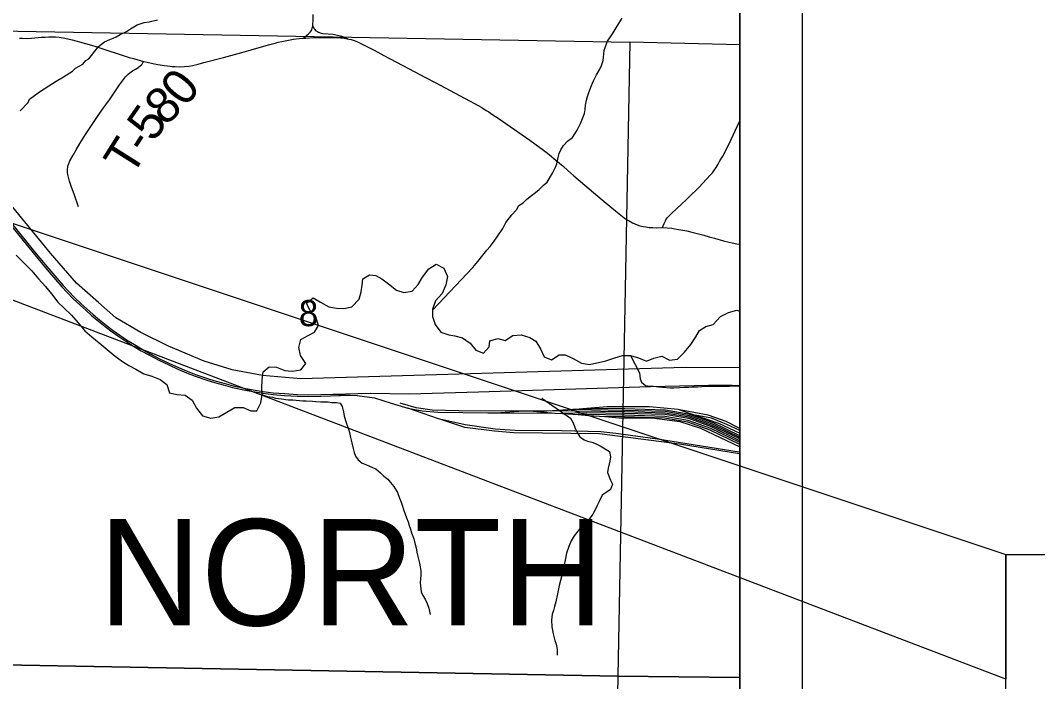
# Model space of a CAD drawing. Extents: x -7.1 to 34, y 0 to 22.
# Drawn here: x 7.746 to 9.377, y 15.673 to 16.733 of the extents above; entities that cross this region are included whole.
import ezdxf

# ---------------------------------------------------------------- set-up
doc = ezdxf.new("R2010")
doc.units = 0
for name, color, linetype in [('GM_X_Major_River', 7, 'Continuous'), ('GM_X_Minor_River', 7, 'Continuous'), ('GM_X_Rail_Line', 7, 'Continuous'), ('GM_X_Section', 7, 'Continuous'), ('GM_X_Section_Text', 7, 'Continuous'), ('GM_X_State_Route', 7, 'Continuous'), ('GM_X_Township_Road', 7, 'Continuous'), ('GM_X_Township_Road_Text', 7, 'Continuous'), ('GM_X_Township_Text', 7, 'Continuous'), ('GM_X_Unincorporated', 7, 'Continuous'), ('SH_Cut_Line', 7, 'Continuous'), ('SH_Data', 7, 'Continuous'), ('SH_Text', 7, 'Continuous')]:
    doc.layers.add(name, color=color, linetype=linetype)

msp = doc.modelspace()

# ---------------------------------------------------------------- linework, layer by layer
at = {"layer": 'GM_X_Major_River'}
for points in [[(7.7396, 16.3561), (7.7523, 16.3433), (7.7646, 16.3309), (7.7757, 16.3182), (7.7865, 16.3058), (7.7962, 16.2942), (7.8066, 16.281), (7.8162, 16.272), (7.8281, 16.26), (7.8393, 16.2477), (7.8497, 16.2349), (7.8608, 16.2252), (7.8727, 16.2158), (7.8857, 16.205), (7.8984, 16.1942), (7.9103, 16.186), (7.9202, 16.1796), (7.9313, 16.1737), (7.9443, 16.1663), (7.9569, 16.1623), (7.9703, 16.1571), (7.9814, 16.1489), (7.9857, 16.1357), (7.9975, 16.1328), (8.0104, 16.1318), (8.0219, 16.124), (8.0289, 16.1108), (8.0386, 16.0988), (8.0515, 16.0948), (8.0644, 16.0972), (8.0772, 16.1046), (8.0904, 16.1119), (8.1034, 16.1121), (8.1159, 16.107), (8.1254, 16.1067), (8.1321, 16.1193), (8.1342, 16.133), (8.1337, 16.1432), (8.1343, 16.1565), (8.1357, 16.1694), (8.1455, 16.1775), (8.1569, 16.1765), (8.1702, 16.1713), (8.1824, 16.1704), (8.196, 16.1724), (8.2039, 16.1828), (8.1957, 16.1956), (8.1926, 16.208), (8.1958, 16.221), (8.2079, 16.2276), (8.2177, 16.2326), (8.2244, 16.2437), (8.2205, 16.2554), (8.2112, 16.2671), (8.2053, 16.2791), (8.2159, 16.2876), (8.2274, 16.2809), (8.2407, 16.2735), (8.2533, 16.2714), (8.2651, 16.2708), (8.2776, 16.2732), (8.2896, 16.2855), (8.2928, 16.2973), (8.2946, 16.3079), (8.2956, 16.3182), (8.3062, 16.3247), (8.3165, 16.3234), (8.326, 16.3182), (8.3364, 16.3103), (8.3494, 16.3002), (8.3612, 16.2962), (8.3745, 16.2983), (8.3842, 16.309), (8.3909, 16.3212), (8.401, 16.3343), (8.4131, 16.342), (8.4253, 16.3353), (8.4312, 16.3221), (8.4283, 16.3088), (8.4228, 16.2947), (8.4119, 16.2832), (8.4071, 16.2699), (8.4073, 16.2581), (8.4112, 16.2449), (8.4205, 16.2328), (8.4334, 16.2285), (8.443, 16.2271), (8.4552, 16.2238), (8.4675, 16.2154)], [(8.4675, 16.2154), (8.4766, 16.2038), (8.4888, 16.199), (8.4981, 16.2094), (8.4991, 16.2189), (8.5119, 16.2225), (8.5237, 16.2197), (8.5357, 16.2275), (8.5493, 16.2285), (8.563, 16.2245), (8.573, 16.2182), (8.5803, 16.2059), (8.5862, 16.1934), (8.5977, 16.1887), (8.61, 16.1965), (8.6199, 16.1963), (8.6325, 16.1904), (8.6462, 16.1831), (8.6591, 16.181), (8.6848, 16.1867), (8.6995, 16.1915), (8.7119, 16.1955), (8.7248, 16.1953), (8.7373, 16.1918), (8.7503, 16.1863), (8.7619, 16.1914), (8.7748, 16.1943), (8.787, 16.188), (8.8002, 16.1894), (8.8114, 16.2009), (8.8214, 16.2129), (8.8292, 16.2255), (8.8354, 16.2355), (8.8452, 16.2421), (8.8569, 16.2453), (8.8688, 16.258), (8.8815, 16.2646), (8.8951, 16.2679), (8.9, 16.2664)]]:
    msp.add_lwpolyline(points, dxfattribs=at)
at = {"layer": 'GM_X_Minor_River'}
for points in [[(8.4071, 16.268), (8.4718, 16.3367), (8.4798, 16.3461), (8.4879, 16.3564), (8.494, 16.364), (8.4997, 16.37), (8.5058, 16.3784), (8.5119, 16.3874), (8.5199, 16.3988), (8.5245, 16.4087), (8.5344, 16.4208), (8.5417, 16.4288), (8.5455, 16.436), (8.5523, 16.4401), (8.5581, 16.4454), (8.5638, 16.45), (8.5725, 16.4568), (8.5782, 16.4617), (8.5847, 16.4678), (8.5908, 16.4734), (8.5996, 16.4879), (8.6046, 16.497), (8.6065, 16.5026), (8.6088, 16.5129), (8.6104, 16.519), (8.6131, 16.525), (8.6173, 16.5319), (8.6237, 16.5387), (8.6314, 16.5447), (8.6356, 16.5508), (8.639, 16.5565), (8.6444, 16.5671), (8.6478, 16.5755), (8.6509, 16.5834), (8.6517, 16.5895), (8.6524, 16.5967), (8.654, 16.6047), (8.6559, 16.6104), (8.6579, 16.6172), (8.6621, 16.6283), (8.6651, 16.6358), (8.6701, 16.6453), (8.6755, 16.6541), (8.6782, 16.6601), (8.6805, 16.6681), (8.682, 16.6787), (8.6824, 16.6844), (8.6844, 16.6905), (8.6878, 16.6992), (8.6924, 16.7064), (8.6966, 16.7125), (8.7016, 16.7205), (8.7058, 16.7273), (8.7111, 16.736)], [(7.7463, 16.5876), (7.759, 16.6011), (7.7608, 16.6061), (7.7773, 16.6178), (7.7919, 16.6275), (7.8039, 16.6349), (7.8155, 16.642), (7.8302, 16.6509), (7.8347, 16.656), (7.8463, 16.6626), (7.8511, 16.6684), (7.856, 16.6707), (7.8605, 16.6765), (7.8657, 16.6831), (7.8716, 16.6904), (7.881, 16.6982), (7.8896, 16.7021), (7.8949, 16.7041), (7.8998, 16.7064), (7.9062, 16.71), (7.9167, 16.7147), (7.9227, 16.719), (7.9336, 16.7256), (7.9449, 16.7292), (7.9528, 16.7301), (7.9664, 16.7333)], [(8.7248, 16.1953), (8.739, 16.1674), (8.7401, 16.1582), (8.742, 16.1525), (8.7484, 16.1476), (8.7556, 16.1464), (8.7617, 16.1464), (8.77, 16.1452), (8.7761, 16.1444), (8.7882, 16.1436), (8.7939, 16.1436), (8.8034, 16.1439), (8.8114, 16.1447), (8.8182, 16.1446), (8.8239, 16.145), (8.8326, 16.1454), (8.8383, 16.1457), (8.847, 16.1461), (8.8599, 16.1464), (8.8835, 16.1463), (8.8952, 16.1467), (8.9, 16.1464)], [(8.1342, 16.133), (8.1346, 16.1322), (8.1425, 16.1297), (8.1505, 16.1286), (8.1555, 16.1272), (8.1653, 16.1258), (8.1756, 16.1244), (8.1831, 16.1242), (8.1937, 16.1232), (8.1991, 16.1229), (8.2047, 16.123), (8.2146, 16.1224), (8.2203, 16.1217), (8.2282, 16.1211), (8.2335, 16.1211), (8.2396, 16.1209), (8.2457, 16.1202), (8.2532, 16.1199), (8.2589, 16.1189), (8.2624, 16.1136), (8.2644, 16.1053), (8.2657, 16.098), (8.2685, 16.0882), (8.2724, 16.0772), (8.274, 16.0719), (8.2756, 16.0639), (8.2777, 16.0552), (8.2797, 16.0461), (8.2813, 16.04), (8.2836, 16.034), (8.2879, 16.028), (8.2944, 16.0231), (8.3005, 16.0205), (8.3112, 16.0161), (8.3161, 16.0139), (8.3238, 16.0076), (8.3292, 16.002), (8.3353, 15.9971), (8.3399, 15.9918), (8.3453, 15.9855), (8.3508, 15.9756), (8.3543, 15.9669), (8.3567, 15.9601), (8.359, 15.9537), (8.3606, 15.9484), (8.3634, 15.9412), (8.3654, 15.9351), (8.3681, 15.9287), (8.3697, 15.923), (8.3717, 15.917), (8.3733, 15.9113), (8.3772, 15.9014), (8.3796, 15.8927), (8.3812, 15.8874), (8.3821, 15.8802), (8.3829, 15.8753), (8.3845, 15.8688), (8.3861, 15.8628), (8.3873, 15.8567), (8.3886, 15.8502), (8.3883, 15.8434), (8.388, 15.8373), (8.3873, 15.8312), (8.3882, 15.8213), (8.389, 15.8164), (8.3918, 15.8107), (8.3956, 15.8051), (8.3988, 15.7979), (8.4015, 15.7907), (8.4024, 15.7857), (8.4032, 15.7804)], [(8.5826, 16.1271), (8.6283, 16.0948), (8.6324, 16.0875), (8.6354, 16.0799), (8.6384, 16.0731), (8.6433, 16.0651), (8.6501, 16.0605), (8.6558, 16.0582), (8.6626, 16.0563), (8.6698, 16.0536), (8.6759, 16.0505), (8.691, 16.0414), (8.6925, 16.033), (8.6917, 16.0258), (8.689, 16.0148), (8.6875, 16.0079), (8.6923, 15.9957), (8.6957, 15.9893), (8.6923, 15.9809), (8.6858, 15.9756), (8.6793, 15.9715), (8.6743, 15.9616), (8.6709, 15.9552), (8.6678, 15.9483), (8.6644, 15.9411), (8.6575, 15.9313), (8.6514, 15.9267), (8.645, 15.9203), (8.6404, 15.9138), (8.6343, 15.9063), (8.6297, 15.8983), (8.6258, 15.8892), (8.622, 15.8786), (8.6201, 15.8672), (8.6185, 15.8603), (8.6173, 15.8539), (8.6143, 15.8429), (8.61, 15.8266), (8.6073, 15.8133), (8.605, 15.8007), (8.603, 15.7931), (8.6011, 15.7867), (8.5988, 15.7806), (8.598, 15.7711), (8.5987, 15.7605), (8.6006, 15.7494), (8.6032, 15.7388), (8.6054, 15.7327), (8.6069, 15.724), (8.6072, 15.715)]]:
    msp.add_lwpolyline(points, dxfattribs=at)
at = {"layer": 'GM_X_Rail_Line'}
for p, q in [((8.2477, 16.1335), (8.2754, 16.1318)), ((8.5093, 16.1033), (8.5453, 16.1063)), ((8.5093, 16.1033), (8.6038, 16.1028)), ((8.5687, 16.1062), (8.5453, 16.1063)), ((8.5687, 16.1062), (8.6038, 16.1028)), ((8.6038, 16.1028), (8.6158, 16.1027)), ((8.6158, 16.1027), (8.6405, 16.1007)), ((8.6545, 16.1105), (8.6359, 16.109)), ((8.8032, 16.1084), (8.8285, 16.0998))]:
    msp.add_line(p, q, dxfattribs=at)
for points in [[(8.9, 16.1755), (8.8125, 16.176), (8.196, 16.1579), (8.1347, 16.1635), (8.0861, 16.1725), (8.0408, 16.1866), (7.984, 16.2103), (7.9395, 16.2321), (7.8997, 16.2558), (7.8718, 16.2805), (7.8362, 16.3111), (7.7949, 16.3595), (7.593, 16.6046)], [(7.7073, 16.433), (7.767, 16.3599), (7.7896, 16.3326), (7.8026, 16.3173), (7.8131, 16.3055), (7.8216, 16.2964), (7.8312, 16.2864), (7.8418, 16.2764), (7.8511, 16.2679), (7.8611, 16.259), (7.8715, 16.2503), (7.8823, 16.2418), (7.8938, 16.2332), (7.9044, 16.2259), (7.9153, 16.2183), (7.9277, 16.2105), (7.9402, 16.2031), (7.9532, 16.1957), (7.9683, 16.1877), (7.9842, 16.1802), (7.9986, 16.1735), (8.0125, 16.1678), (8.0264, 16.1625), (8.0454, 16.1559), (8.0576, 16.1521), (8.0716, 16.1482), (8.0867, 16.1442), (8.1045, 16.1403), (8.1191, 16.1375), (8.1354, 16.1348), (8.1517, 16.133), (8.1696, 16.1315), (8.1904, 16.1302), (8.2088, 16.1298), (8.2283, 16.1301), (8.2754, 16.1318)], [(7.7095, 16.4348), (7.7692, 16.3616), (7.7918, 16.3344), (7.8048, 16.3192), (7.8152, 16.3074), (7.8236, 16.2983), (7.8332, 16.2885), (7.8438, 16.2784), (7.853, 16.27), (7.8629, 16.2611), (7.8733, 16.2525), (7.884, 16.244), (7.8954, 16.2355), (7.906, 16.2282), (7.9168, 16.2207), (7.9292, 16.2129), (7.9416, 16.2055), (7.9545, 16.1981), (7.9695, 16.1902), (7.9854, 16.1827), (7.9997, 16.1761), (8.0136, 16.1705), (8.0274, 16.1652), (8.0463, 16.1586), (8.0584, 16.1548), (8.0724, 16.151), (8.0874, 16.147), (8.1051, 16.143), (8.1196, 16.1403), (8.1358, 16.1376), (8.1519, 16.1358), (8.1698, 16.1344), (8.1905, 16.133), (8.2088, 16.1326), (8.2282, 16.1329), (8.3074, 16.1351), (8.3695, 16.1341), (8.4807, 16.1372), (8.6372, 16.1419), (8.7565, 16.1456), (8.8266, 16.1473), (8.8496, 16.1477), (8.8703, 16.148), (8.8877, 16.148), (8.9, 16.1473)], [(8.2754, 16.1318), (8.2864, 16.1312), (8.314, 16.1276), (8.341, 16.1188), (8.3674, 16.1112)], [(8.5453, 16.1063), (8.4493, 16.1067), (8.4066, 16.108), (8.381, 16.1114), (8.3555, 16.1192)], [(8.419, 16.0934), (8.417, 16.0938), (8.3674, 16.1112)], [(8.3674, 16.1112), (8.3906, 16.1068), (8.4157, 16.1047), (8.496, 16.1034), (8.5093, 16.1033)], [(8.5994, 16.1067), (8.5902, 16.1061), (8.5687, 16.1062)], [(8.6359, 16.109), (8.6321, 16.1087), (8.5994, 16.1067)], [(8.9, 16.0616), (8.8552, 16.0833), (8.8185, 16.0965), (8.7801, 16.103), (8.7152, 16.105), (8.5994, 16.1067)], [(8.9, 16.0589), (8.8543, 16.0811), (8.8179, 16.0942), (8.7798, 16.1007), (8.7151, 16.1027), (8.6544, 16.1034), (8.6158, 16.1027)], [(8.9, 16.0642), (8.8561, 16.0855), (8.8191, 16.0988), (8.7803, 16.1054), (8.7152, 16.1074), (8.6359, 16.109)], [(8.9, 16.0558), (8.8532, 16.0785), (8.8172, 16.0915), (8.7795, 16.0979), (8.7151, 16.0998), (8.6544, 16.1006), (8.6405, 16.1007)], [(8.6405, 16.1007), (8.6575, 16.0994), (8.6834, 16.0974)], [(8.8032, 16.1084), (8.8008, 16.1088), (8.7551, 16.1133), (8.6874, 16.1131), (8.6545, 16.1105)], [(8.9, 16.0668), (8.8571, 16.0877), (8.8198, 16.1011), (8.7805, 16.1077), (8.7153, 16.1097), (8.6545, 16.1105)], [(8.9, 16.0786), (8.8781, 16.0895), (8.8489, 16.1), (8.8032, 16.1084)], [(8.9, 16.0751), (8.8792, 16.085), (8.8542, 16.0951), (8.8285, 16.0998)], [(8.8285, 16.0998), (8.8659, 16.0871), (8.8997, 16.0711), (8.9, 16.071)], [(8.9, 16.0376), (8.8994, 16.0377), (8.8031, 16.0533), (8.675, 16.0698), (8.5375, 16.0714), (8.5064, 16.074), (8.4589, 16.0802), (8.419, 16.0934)], [(8.9, 16.0404), (8.8988, 16.0407), (8.7679, 16.0615), (8.7013, 16.0704), (8.6769, 16.0733), (8.6147, 16.0746), (8.5397, 16.0752), (8.5076, 16.0772), (8.4593, 16.0845), (8.419, 16.0934)], [(8.9, 16.0526), (8.8521, 16.0759), (8.8165, 16.0887), (8.7793, 16.095), (8.715, 16.097), (8.6834, 16.0974)], [(8.6834, 16.0974), (8.7065, 16.0956), (8.7589, 16.0954), (8.8036, 16.0894), (8.8366, 16.0789), (8.9, 16.049)]]:
    msp.add_lwpolyline(points, dxfattribs=at)
at = {"layer": 'GM_X_Section'}
for points in [[(7.7117, 16.7156), (8.7236, 16.6977), (8.7045, 15.6816), (7.6901, 15.7003)], [(7.6901, 15.7003), (8.7045, 15.6816), (8.6861, 14.6719), (7.6641, 14.6933)]]:
    msp.add_lwpolyline(points, close=True, dxfattribs=at)
at = {"layer": 'GM_X_State_Route'}
for points in [[(7.7448, 16.704), (7.749, 16.7038), (7.7564, 16.7037), (7.7643, 16.7041), (7.7801, 16.7054), (7.786, 16.7058), (7.792, 16.7061), (7.7964, 16.7061), (7.8027, 16.7059), (7.8084, 16.7054), (7.8148, 16.7045), (7.8223, 16.7031), (7.8293, 16.7015), (7.841, 16.6984), (7.8603, 16.6928), (7.8673, 16.6906), (7.9207, 16.6733), (7.9276, 16.6712), (7.944, 16.6668), (7.9497, 16.6654), (7.9586, 16.6633), (7.9668, 16.6618), (7.9776, 16.6602), (7.986, 16.6589), (7.9892, 16.6586), (7.9948, 16.6584), (8.0022, 16.6583), (8.0097, 16.6586), (8.0167, 16.6594), (8.0225, 16.6604), (8.0316, 16.6624), (8.0404, 16.6648), (8.0721, 16.6729), (8.1017, 16.6812), (8.1162, 16.6851), (8.1443, 16.6932), (8.1549, 16.6962), (8.1596, 16.6974), (8.1654, 16.6988), (8.1788, 16.7014), (8.1842, 16.7022), (8.1932, 16.7033), (8.2, 16.7039), (8.2037, 16.7042), (8.2168, 16.7049), (8.239, 16.7052), (8.2525, 16.7049), (8.2597, 16.7045), (8.2653, 16.7039), (8.2706, 16.703)], [(8.2706, 16.703), (8.2731, 16.7026), (8.2766, 16.7017), (8.2814, 16.7002), (8.2871, 16.6981), (8.2913, 16.6962), (8.3052, 16.6892), (8.3138, 16.6847), (8.3293, 16.6765), (8.3687, 16.6555), (8.396, 16.6408), (8.4124, 16.6323), (8.4584, 16.6081), (8.4756, 16.599), (8.4862, 16.5928), (8.4934, 16.5882), (8.4973, 16.5857), (8.5024, 16.5823), (8.5126, 16.5757), (8.5317, 16.5625), (8.5509, 16.5492), (8.5632, 16.5405), (8.5736, 16.5332), (8.583, 16.5261), (8.5915, 16.5197), (8.605, 16.5085), (8.6165, 16.4987), (8.6242, 16.4918), (8.6339, 16.4832), (8.6581, 16.4623), (8.6791, 16.445), (8.6947, 16.432), (8.7063, 16.4226), (8.712, 16.4182), (8.7168, 16.4146), (8.7225, 16.411), (8.7277, 16.4081), (8.7313, 16.4064), (8.7353, 16.4048), (8.7397, 16.4034), (8.7449, 16.4022), (8.7494, 16.4014), (8.7547, 16.4008), (8.76, 16.4004), (8.7661, 16.4003), (8.7758, 16.4004)], [(8.7758, 16.4004), (8.7835, 16.4001), (8.7909, 16.3993), (8.7959, 16.3986), (8.8018, 16.3976), (8.8053, 16.3969), (8.8147, 16.3952), (8.8253, 16.3925), (8.842, 16.3881), (8.8505, 16.3856), (8.859, 16.3833), (8.8737, 16.3792), (8.8826, 16.377), (8.8877, 16.3759), (8.8951, 16.3746), (8.9, 16.3738)]]:
    msp.add_lwpolyline(points, dxfattribs=at)
at = {"layer": 'GM_X_Township_Road'}
msp.add_lwpolyline([(6.633, 14.1), (8.9, 14.1), (8.9, 17.7079), (8.6668, 17.7136), (8.4472, 17.7189), (7.7202, 17.7285), (6.7118, 17.7486), (6.7058, 17.2839), (6.6822, 16.3488), (6.6748, 15.9993), (6.6586, 15.2372), (6.6565, 15.1357)], close=True, dxfattribs=at)
for points in [[(8.2, 16.7039), (8.203, 16.7061), (8.2058, 16.7086), (8.2086, 16.7111), (8.2108, 16.7134), (8.213, 16.7162), (8.2139, 16.718), (8.2144, 16.7199), (8.2152, 16.7232), (8.2154, 16.7277), (8.2156, 16.7307), (8.216, 16.7421)], [(8.2152, 16.7232), (8.2165, 16.7206), (8.218, 16.7182), (8.2202, 16.716), (8.2225, 16.7145), (8.2245, 16.7135), (8.2286, 16.7122), (8.2314, 16.7115), (8.2477, 16.7102), (8.2499, 16.7099), (8.2595, 16.7079), (8.2618, 16.7073), (8.2642, 16.7064), (8.2669, 16.7052), (8.2685, 16.7043), (8.2706, 16.703)], [(7.8396, 16.4338), (7.8325, 16.4538), (7.8284, 16.4654), (7.8254, 16.4748), (7.8237, 16.4811), (7.8226, 16.4857), (7.8221, 16.4889), (7.8218, 16.4925), (7.8224, 16.4988), (7.824, 16.5029), (7.8257, 16.5072), (7.831, 16.5167), (7.8357, 16.5249), (7.8416, 16.535), (7.8498, 16.5479), (7.8625, 16.5674), (7.8701, 16.5786), (7.8795, 16.5921), (7.8891, 16.6054), (7.9052, 16.6293), (7.9152, 16.6422), (7.9187, 16.6458), (7.9219, 16.6486), (7.9261, 16.6515), (7.9314, 16.6546), (7.9354, 16.6571), (7.9392, 16.6601), (7.9407, 16.6615), (7.9415, 16.6626), (7.944, 16.6668)], [(8.7758, 16.4004), (8.7787, 16.4071), (8.7795, 16.4091), (8.7805, 16.4113), (8.7815, 16.4131), (8.7824, 16.4145), (8.7839, 16.4164), (8.7864, 16.419), (8.7907, 16.4233), (8.8063, 16.4379), (8.8145, 16.4457), (8.8182, 16.4493), (8.834, 16.4649), (8.8464, 16.478), (8.8528, 16.4849), (8.8559, 16.4883), (8.8582, 16.4916), (8.8617, 16.4967), (8.8649, 16.5022), (8.8679, 16.5073), (8.8724, 16.5149), (8.8815, 16.5326), (8.8855, 16.5406), (8.8964, 16.5637), (8.9, 16.5713)]]:
    msp.add_lwpolyline(points, dxfattribs=at)
at = {"layer": 'GM_X_Unincorporated'}
for points in [[(8.9, 15.6794), (8.9, 16.6936), (8.7236, 16.6977), (8.7045, 15.6816)], [(8.9, 14.6715), (8.9, 15.6794), (8.7045, 15.6816), (8.6861, 14.6719)]]:
    msp.add_lwpolyline(points, close=True, dxfattribs=at)
at = {"layer": 'SH_Cut_Line'}
msp.add_lwpolyline([(2.1, 17.7253), (2.1, 14.1), (8.9, 14.1), (8.9, 17.7079), (8.6668, 17.7136), (8.4472, 17.7189), (7.7202, 17.7285), (6.7118, 17.7486), (6.3575, 17.7557), (6.1904, 17.7592), (5.7514, 17.7685), (5.5047, 17.7737), (5.1115, 17.7819), (5.0544, 17.7831), (5.0443, 17.7832), (4.7094, 17.7848), (4.5657, 17.7857), (4.3, 17.7873), (3.8304, 17.7952), (3.8238, 17.6717), (3.7215, 17.6707), (3.0659, 17.6986), (2.7886, 17.7105), (2.5551, 17.7155)], close=True, dxfattribs=at)
at = {"layer": 'SH_Data'}
for p, q in [((9, 21), (9, 14)), ((8.9, 20.9), (8.9, 14.1))]:
    msp.add_line(p, q, dxfattribs=at)
at = {"layer": 'SH_Text'}
for points in [[(5.1735, 17.2614), (9.3262, 15.8766), (9.3261, 15.6767)], [(9.3262, 15.8766), (10.9505, 15.8766), (10.9505, 15.3766), (9.3262, 15.3766)]]:
    msp.add_lwpolyline(points, close=True, dxfattribs=at)

# ---------------------------------------------------------------- texts
at = {"layer": 'GM_X_Section_Text'}
msp.add_text('8', height=0.0419, rotation=0, dxfattribs=at).set_placement((8.1928, 16.2424))
at = {"layer": 'GM_X_Township_Road_Text'}
for s, rotation, p in [('0', 50.5639, (8.0104, 16.5919)), ('8', 41.9002, (7.9778, 16.5618)), ('5', 55.2245, (7.9602, 16.5357)), ('T', 57.7852, (7.9251, 16.4807)), ('-', 56.8122, (7.9476, 16.5165))]:
    msp.add_text(s, height=0.0568, rotation=rotation, dxfattribs=at).set_placement(p)
at = {"layer": 'GM_X_Township_Text'}
msp.add_text('NORTH', height=0.17045, rotation=0, dxfattribs=at).set_placement((7.8719, 15.7627))

doc.saveas('drawing.dxf')
